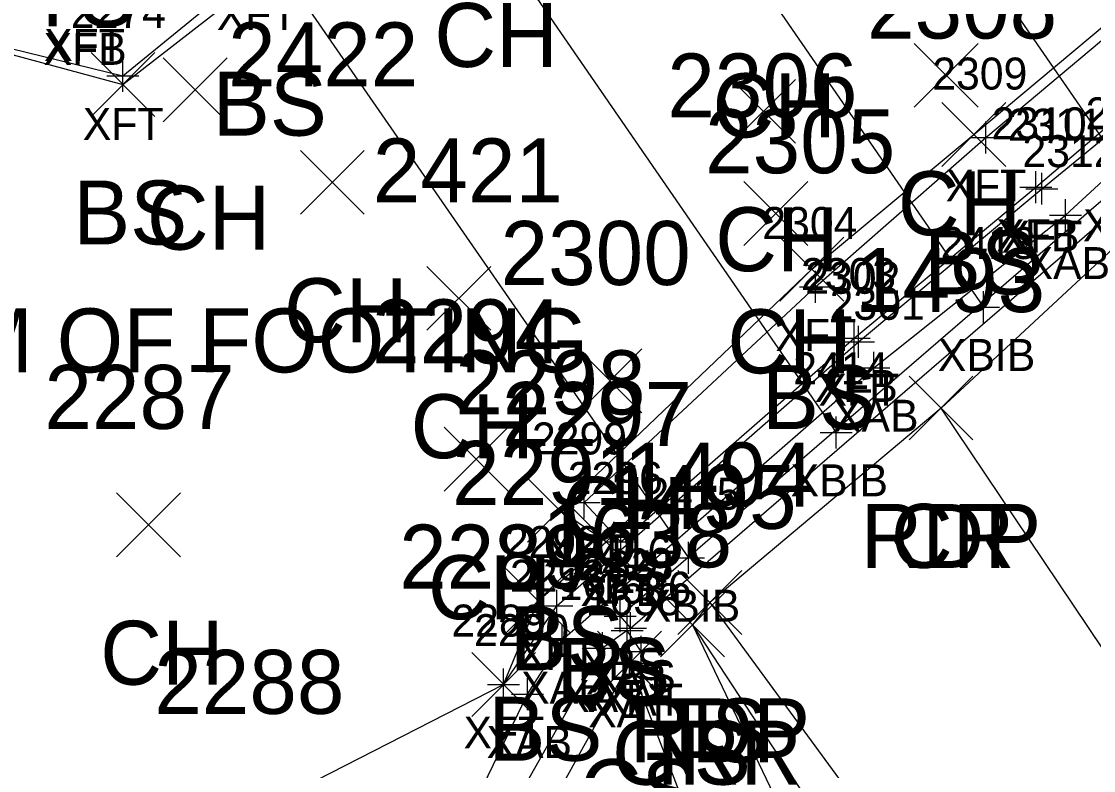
# Model space of a CAD drawing. Extents: x 1501299 to 1502485, y 381423 to 383765.
# Drawn here: x 1501597.62 to 1501631.17, y 383276.54 to 383299.97 of the extents above; entities that cross this region are included whole.
import ezdxf

# ---------------------------------------------------------------- set-up
doc = ezdxf.new("R2010")
doc.units = 0
for name, color, linetype in [('B_A', 7, 'Continuous'), ('B_I', 7, 'Continuous'), ('B_TIC', 7, 'Continuous'), ('BB', 7, 'Continuous'), ('BFT', 7, 'Continuous'), ('BSE', 7, 'Continuous'), ('BSUBM', 7, 'Continuous'), ('L_A', 7, 'Continuous'), ('L_C', 7, 'Continuous'), ('L_I', 7, 'Continuous'), ('L_TIC', 7, 'Continuous'), ('LELB', 7, 'Continuous'), ('P_A', 7, 'Continuous'), ('P_I', 7, 'Continuous'), ('P_TIC', 7, 'Continuous'), ('PET', 7, 'Continuous'), ('PRC', 7, 'Continuous'), ('R_A', 7, 'Continuous'), ('R_I', 7, 'Continuous'), ('R_TIC', 7, 'Continuous'), ('RGR', 7, 'Continuous')]:
    doc.layers.add(name, color=color, linetype=linetype)

msp = doc.modelspace()

# ---------------------------------------------------------------- linework, layer by layer
at = {"layer": 'B_TIC'}
for p, q in [((1501600.797, 383298.267), (1501600.873, 383298.267)), ((1501627.794, 383296.339), (1501627.87, 383296.339)), ((1501629.366, 383294.783), (1501629.442, 383294.783)), ((1501629.546, 383294.74), (1501629.622, 383294.74)), ((1501630.291, 383293.913), (1501630.367, 383293.913)), ((1501622.473, 383291.667), (1501622.548, 383291.667)), ((1501627.725, 383291.039), (1501627.801, 383291.039)), ((1501623.682, 383290.07), (1501623.758, 383290.07)), ((1501623.816, 383289.953), (1501623.892, 383289.953)), ((1501624.296, 383289.139), (1501624.372, 383289.139)), ((1501623.118, 383287.119), (1501623.193, 383287.119)), ((1501615.23, 383284.929), (1501615.305, 383284.929)), ((1501616.373, 383283.693), (1501616.448, 383283.693)), ((1501616.373, 383283.693), (1501616.448, 383283.693)), ((1501618.494, 383283.2), (1501618.57, 383283.2)), ((1501614.377, 383281.692), (1501614.453, 383281.692)), ((1501616.353, 383281.373), (1501616.428, 383281.373)), ((1501616.577, 383280.924), (1501616.653, 383280.924)), ((1501616.679, 383280.995), (1501616.755, 383280.995)), ((1501614.537, 383280.635), (1501614.613, 383280.635)), ((1501615.804, 383280.376), (1501615.88, 383280.376)), ((1501615.804, 383280.376), (1501615.88, 383280.376)), ((1501617.012, 383280.262), (1501617.088, 383280.262)), ((1501617.012, 383280.262), (1501617.088, 383280.262)), ((1501616.652, 383279.899), (1501616.727, 383279.899)), ((1501612.71, 383279.234), (1501612.786, 383279.234)), ((1501613.455, 383278.934), (1501613.53, 383278.934))]:
    msp.add_line(p, q, dxfattribs=at)
for points in [[(1501600.794, 383297.767), (1501600.794, 383298.767)], [(1501600.294, 383298.267), (1501601.294, 383298.267)], [(1501627.791, 383295.839), (1501627.791, 383296.839)], [(1501627.291, 383296.339), (1501628.291, 383296.339)], [(1501629.363, 383294.283), (1501629.363, 383295.283)], [(1501629.543, 383294.24), (1501629.543, 383295.24)], [(1501628.863, 383294.783), (1501629.863, 383294.783)], [(1501629.043, 383294.74), (1501630.043, 383294.74)], [(1501630.288, 383293.413), (1501630.288, 383294.413)], [(1501629.788, 383293.913), (1501630.788, 383293.913)], [(1501622.469, 383291.167), (1501622.469, 383292.167)], [(1501621.969, 383291.667), (1501622.969, 383291.667)], [(1501627.722, 383290.539), (1501627.722, 383291.539)], [(1501627.222, 383291.039), (1501628.222, 383291.039)], [(1501623.679, 383289.57), (1501623.679, 383290.57)], [(1501623.813, 383289.453), (1501623.813, 383290.453)], [(1501623.179, 383290.07), (1501624.179, 383290.07)], [(1501623.313, 383289.953), (1501624.313, 383289.953)], [(1501624.293, 383288.639), (1501624.293, 383289.639)], [(1501623.793, 383289.139), (1501624.793, 383289.139)], [(1501623.114, 383286.619), (1501623.114, 383287.619)], [(1501622.614, 383287.119), (1501623.614, 383287.119)], [(1501615.226, 383284.429), (1501615.226, 383285.429)], [(1501614.726, 383284.929), (1501615.726, 383284.929)], [(1501616.369, 383283.193), (1501616.369, 383284.193)], [(1501616.369, 383283.193), (1501616.369, 383284.193)], [(1501615.869, 383283.693), (1501616.869, 383283.693)], [(1501615.869, 383283.693), (1501616.869, 383283.693)], [(1501618.491, 383282.7), (1501618.491, 383283.7)], [(1501617.991, 383283.2), (1501618.991, 383283.2)], [(1501614.374, 383281.192), (1501614.374, 383282.192)], [(1501616.349, 383280.873), (1501616.349, 383281.873)], [(1501613.874, 383281.692), (1501614.874, 383281.692)], [(1501616.574, 383280.424), (1501616.574, 383281.424)], [(1501616.676, 383280.495), (1501616.676, 383281.495)], [(1501614.534, 383280.135), (1501614.534, 383281.135)], [(1501615.849, 383281.373), (1501616.849, 383281.373)], [(1501615.801, 383279.876), (1501615.801, 383280.876)], [(1501615.801, 383279.876), (1501615.801, 383280.876)], [(1501616.074, 383280.924), (1501617.074, 383280.924)], [(1501616.176, 383280.995), (1501617.176, 383280.995)], [(1501617.009, 383279.762), (1501617.009, 383280.762)], [(1501617.009, 383279.762), (1501617.009, 383280.762)], [(1501614.034, 383280.635), (1501615.034, 383280.635)], [(1501616.648, 383279.399), (1501616.648, 383280.399)], [(1501615.301, 383280.376), (1501616.301, 383280.376)], [(1501615.301, 383280.376), (1501616.301, 383280.376)], [(1501616.509, 383280.262), (1501617.509, 383280.262)], [(1501616.509, 383280.262), (1501617.509, 383280.262)], [(1501612.707, 383278.734), (1501612.707, 383279.734)], [(1501616.148, 383279.899), (1501617.148, 383279.899)], [(1501613.451, 383278.434), (1501613.451, 383279.434)], [(1501612.207, 383279.234), (1501613.207, 383279.234)], [(1501612.951, 383278.934), (1501613.951, 383278.934)]]:
    msp.add_lwpolyline(points, dxfattribs=at)
at = {"layer": 'BB'}
for points in [[(1501616.9, 383317.377), (1501632.264, 383295.097)], [(1501612.287, 383313.43), (1501627.722, 383291.039)], [(1501607.665, 383309.53), (1501623.114, 383287.119)], [(1501603.072, 383305.463), (1501618.491, 383283.2)]]:
    msp.add_lwpolyline(points, dxfattribs=at)
at = {"layer": 'BFT'}
for points in [[(1501590.258, 383300.858), (1501600.794, 383298.267), (1501604.985, 383301.7), (1501610.419, 383306.178), (1501616.429, 383311.032), (1501623.09, 383316.78), (1501624.747, 383320.366)], [(1501616.369, 383283.693), (1501615.226, 383284.929), (1501622.469, 383291.667), (1501627.791, 383296.339), (1501634.323, 383301.827), (1501643.966, 383300.613), (1501649.637, 383299.733), (1501649.406, 383298.057)], [(1501616.369, 383283.693), (1501623.679, 383290.07), (1501629.363, 383294.783), (1501635.405, 383299.935), (1501649.406, 383298.057)], [(1501612.707, 383279.234), (1501614.374, 383281.692), (1501623.813, 383289.953), (1501629.543, 383294.74), (1501635.454, 383299.572), (1501649.389, 383297.783), (1501649.431, 383296.917)]]:
    msp.add_lwpolyline(points, dxfattribs=at)
at = {"layer": 'BSE'}
msp.add_lwpolyline([(1501634.051, 383296.635), (1501616.349, 383281.373), (1501616.676, 383280.995), (1501634.378, 383296.256)], dxfattribs=at)
at = {"layer": 'BSUBM'}
for points in [[(1501610.098, 383268.035), (1501609.905, 383267.245), (1501608.382, 383268.462), (1501613.451, 383278.934), (1501614.534, 383280.635), (1501624.293, 383289.139), (1501630.288, 383293.913), (1501635.348, 383298.565), (1501649.431, 383296.917), (1501649.596, 383294.923)], [(1501617.009, 383280.262), (1501616.574, 383280.924), (1501615.801, 383280.376)], [(1501617.009, 383280.262), (1501616.648, 383279.899), (1501610.098, 383268.035), (1501609.218, 383268.708), (1501615.801, 383280.376)]]:
    msp.add_lwpolyline(points, dxfattribs=at)
at = {"layer": 'L_TIC'}
for points in [[(1501625.553, 383297.285), (1501627.553, 383299.285)], [(1501627.553, 383297.285), (1501625.553, 383299.285)], [(1501599.796, 383296.995), (1501601.796, 383298.995)], [(1501601.796, 383296.995), (1501599.796, 383298.995)], [(1501602.055, 383296.833), (1501604.055, 383298.833)], [(1501604.055, 383296.833), (1501602.055, 383298.833)], [(1501619.838, 383296.159), (1501621.838, 383298.159)], [(1501621.838, 383296.159), (1501619.838, 383298.159)], [(1501626.416, 383295.435), (1501628.416, 383297.435)], [(1501628.416, 383295.435), (1501626.416, 383297.435)], [(1501606.346, 383293.939), (1501608.346, 383295.939)], [(1501608.346, 383293.939), (1501606.346, 383295.939)], [(1501620.22, 383292.966), (1501622.22, 383294.966)], [(1501622.22, 383292.966), (1501620.22, 383294.966)], [(1501621.35, 383291.222), (1501623.35, 383293.222)], [(1501623.35, 383291.222), (1501621.35, 383293.222)], [(1501610.307, 383290.311), (1501612.307, 383292.311)], [(1501612.307, 383290.311), (1501610.307, 383292.311)], [(1501615.036, 383287.728), (1501617.036, 383289.728)], [(1501617.036, 383287.728), (1501615.036, 383289.728)], [(1501610.848, 383285.277), (1501612.848, 383287.277)], [(1501612.848, 383285.277), (1501610.848, 383287.277)], [(1501613.455, 383283.683), (1501615.455, 383285.683)], [(1501615.455, 383283.683), (1501613.455, 383285.683)], [(1501600.596, 383283.228), (1501602.596, 383285.228)], [(1501602.596, 383283.228), (1501600.596, 383285.228)], [(1501614.914, 383282.693), (1501616.914, 383284.693)], [(1501616.914, 383282.693), (1501614.914, 383284.693)], [(1501612.789, 383280.85), (1501614.789, 383282.85)], [(1501614.789, 383280.85), (1501612.789, 383282.85)], [(1501618.162, 383280.8), (1501620.162, 383282.8)], [(1501620.162, 383280.8), (1501618.162, 383282.8)], [(1501617.614, 383280.102), (1501619.614, 383282.102)], [(1501619.614, 383280.102), (1501617.614, 383282.102)], [(1501615.648, 383278.899), (1501617.648, 383280.899)], [(1501617.648, 383278.899), (1501615.648, 383280.899)], [(1501611.707, 383278.234), (1501613.707, 383280.234)], [(1501613.707, 383278.234), (1501611.707, 383280.234)]]:
    msp.add_lwpolyline(points, dxfattribs=at)
at = {"layer": 'LELB'}
for points in [[(1501590.761, 383266.457), (1501598.871, 383270.571), (1501605.035, 383275.317), (1501612.707, 383279.234), (1501613.789, 383281.85), (1501615.914, 383283.693), (1501614.455, 383284.683), (1501622.35, 383292.222), (1501627.416, 383296.435), (1501634.13, 383302.054), (1501643.772, 383300.983), (1501650.033, 383300.072), (1501651.493, 383297.792), (1501662.757, 383297.227), (1501671.557, 383298.422), (1501684.76, 383303.845), (1501698.893, 383313.194), (1501704.538, 383312.156), (1501711.847, 383316.203), (1501724.827, 383323.61), (1501744.215, 383336.813), (1501764.443, 383344.5)], [(1501498.194, 383229.3), (1501506.162, 383243.777), (1501514.118, 383255.518), (1501521.598, 383264.924), (1501530.006, 383266.909), (1501541.24, 383276.124), (1501565.518, 383288.263), (1501578.593, 383296.727), (1501585.352, 383299.258), (1501590.258, 383300.858), (1501600.796, 383297.995), (1501605.166, 383301.398), (1501610.699, 383306.054), (1501616.468, 383310.93), (1501623.409, 383316.642), (1501624.747, 383320.366)], [(1501619.162, 383281.8), (1501618.614, 383281.102), (1501625.909, 383269.987), (1501629.163, 383260.706), (1501626.947, 383253.594), (1501623.522, 383242.303), (1501612.249, 383228.196), (1501584.091, 383204.532), (1501565.556, 383192.677), (1501531.011, 383172.484)], [(1501616.648, 383279.899), (1501621.389, 383267.635), (1501624.053, 383260.203), (1501618.219, 383246.655), (1501610.438, 383240.687), (1501605.349, 383233.312)]]:
    msp.add_lwpolyline(points, dxfattribs=at)
at = {"layer": 'P_TIC'}
for points in [[(1501625.393, 383286.881), (1501627.393, 383288.881)], [(1501627.393, 383286.881), (1501625.393, 383288.881)], [(1501625.393, 383286.881), (1501627.393, 383288.881)], [(1501627.393, 383286.881), (1501625.393, 383288.881)], [(1501618.162, 383280.8), (1501620.162, 383282.8)], [(1501620.162, 383280.8), (1501618.162, 383282.8)]]:
    msp.add_lwpolyline(points, dxfattribs=at)
at = {"layer": 'PET'}
msp.add_lwpolyline([(1501787.994, 383066.094), (1501768.484, 383096.751), (1501754.41, 383116.891), (1501736.241, 383144.717), (1501720.749, 383167.971), (1501712.594, 383179.719), (1501694.383, 383207.646), (1501673.597, 383237.523), (1501647.754, 383273.845), (1501633.679, 383294.635), (1501626.393, 383287.881), (1501619.162, 383281.8), (1501626.926, 383271.201), (1501654.425, 383229.168), (1501675.697, 383198.288), (1501696.699, 383166.339)], dxfattribs=at)
at = {"layer": 'PRC'}
msp.add_lwpolyline([(1501960.612, 382718.648), (1501950.96, 382750.482), (1501934.965, 382791.852), (1501913.074, 382836.935), (1501889.309, 382881.383), (1501879.244, 382899.507), (1501856.391, 382940.32), (1501839.674, 382966.998), (1501816.055, 383004.313), (1501794.783, 383036.247), (1501769.812, 383075.158), (1501745.791, 383111.558), (1501729.435, 383136.001), (1501711.236, 383163.535), (1501694.816, 383188.199), (1501683.547, 383204.004), (1501664.644, 383231.239), (1501639.517, 383268.342), (1501626.393, 383287.881)], dxfattribs=at)
at = {"layer": 'R_TIC'}
for points in [[(1501617.614, 383280.102), (1501619.614, 383282.102)], [(1501619.614, 383280.102), (1501617.614, 383282.102)]]:
    msp.add_lwpolyline(points, dxfattribs=at)
at = {"layer": 'RGR'}
msp.add_lwpolyline([(1501618.614, 383281.102), (1501624.041, 383269.773)], dxfattribs=at)

# ---------------------------------------------------------------- texts
at = {"layer": 'B_A'}
for s, p in [('XFT', (1501603.729, 383299.7)), ('XFB', (1501598.311, 383298.612)), ('XFT', (1501598.328, 383298.737)), ('XFT', (1501599.538, 383296.267)), ('XFT', (1501626.535, 383294.339)), ('XBIB', (1501630.835, 383293.097)), ('XFB', (1501628.122, 383292.783)), ('XFT', (1501628.287, 383292.74)), ('XAB', (1501629.008, 383291.913)), ('XFT', (1501621.214, 383289.667)), ('XBIB', (1501626.293, 383289.039)), ('XFB', (1501622.439, 383288.07)), ('XFT', (1501622.557, 383287.953)), ('XAB', (1501623.013, 383287.139)), ('XBIB', (1501621.685, 383285.119)), ('XFT', (1501613.97, 383282.929)), ('XFT', (1501615.113, 383281.693)), ('XFB', (1501615.129, 383281.693)), ('XBIB', (1501617.062, 383281.2)), ('XFT', (1501613.118, 383279.692)), ('XBS', (1501615.089, 383279.373)), ('XAT', (1501615.279, 383278.924)), ('XBS', (1501615.416, 383278.995)), ('XAB', (1501613.254, 383278.635)), ('XAT', (1501614.505, 383278.376)), ('XAT', (1501614.505, 383278.376)), ('XAT', (1501615.714, 383278.262)), ('XAT', (1501615.714, 383278.262)), ('XAT', (1501615.353, 383277.899)), ('XFT', (1501611.451, 383277.234)), ('XAB', (1501612.172, 383276.934))]:
    msp.add_text(s, height=1, dxfattribs=at).set_placement(p)
at = {"layer": 'B_I'}
for s, p in [('2274', (1501599.164, 383299.767)), ('2309', (1501626.118, 383297.839)), ('2412', (1501630.918, 383296.597)), ('2310', (1501627.973, 383296.283)), ('2311', (1501628.48, 383296.24)), ('2312', (1501628.941, 383295.413)), ('2304', (1501620.8, 383293.167)), ('2413', (1501626.375, 383292.539)), ('2303', (1501622.01, 383291.57)), ('2302', (1501622.144, 383291.453)), ('2301', (1501622.907, 383290.639)), ('2414', (1501621.768, 383288.619)), ('2299', (1501613.592, 383286.429)), ('2296', (1501614.712, 383285.193)), ('2296', (1501614.712, 383285.193)), ('2415', (1501617.144, 383284.7)), ('2292', (1501612.744, 383283.192)), ('2416', (1501614.975, 383282.873)), ('2428', (1501615.046, 383282.495)), ('1637', (1501615.204, 383282.424)), ('2293', (1501612.904, 383282.135)), ('1687', (1501614.431, 383281.876)), ('1687', (1501614.431, 383281.876)), ('1636', (1501615.611, 383281.762)), ('1636', (1501615.611, 383281.762)), ('1638', (1501615.278, 383281.399)), ('2289', (1501611.073, 383280.734)), ('2290', (1501611.778, 383280.434))]:
    msp.add_text(s, height=1, dxfattribs=at).set_placement(p)
at = {"layer": 'L_A'}
for s, p in [('TS', (1501597.779, 383299.818)), ('CH', (1501610.539, 383298.546)), ('BS', (1501603.607, 383296.398)), ('CH', (1501619.242, 383296.345)), ('CH', (1501625.041, 383293.285)), ('BS', (1501599.237, 383292.995)), ('CH', (1501601.544, 383292.833)), ('CH', (1501619.326, 383292.159)), ('BS', (1501625.857, 383291.435)), ('CH', (1501605.835, 383289.939)), ('CH', (1501619.709, 383288.966)), ('BS', (1501620.791, 383287.222)), ('CH', (1501609.795, 383286.311)), ('CH', (1501614.524, 383283.728)), ('CH', (1501610.336, 383281.277)), ('BS', (1501612.896, 383279.683)), ('CH', (1501600.084, 383279.228)), ('BS', (1501614.355, 383278.693)), ('BS', (1501612.23, 383276.85)), ('TS', (1501617.571, 383276.8)), ('TS', (1501617.024, 383276.102)), ('CS', (1501615.089, 383274.899))]:
    msp.add_text(s, height=2, dxfattribs=at).set_placement(p)
at = {"layer": 'L_C'}
msp.add_text('AT BOTTOM OF FOOTING', height=2, dxfattribs=at).set_placement((1501582.379, 383288.995))
at = {"layer": 'L_I'}
for s, p in [('2308', (1501624.078, 383299.435)), ('2422', (1501604.087, 383297.939)), ('2306', (1501617.827, 383296.966)), ('2305', (1501619.011, 383295.222)), ('2421', (1501608.614, 383294.311)), ('2300', (1501612.611, 383291.728)), ('2294', (1501608.588, 383289.277)), ('2298', (1501611.196, 383287.683)), ('2287', (1501598.336, 383287.228)), ('2297', (1501612.654, 383286.693)), ('2291', (1501611.096, 383284.85)), ('1494', (1501616.469, 383284.8)), ('1495', (1501615.921, 383284.102)), ('1638', (1501613.908, 383282.899)), ('2289', (1501609.439, 383282.234)), ('2288', (1501601.775, 383278.317))]:
    msp.add_text(s, height=2, dxfattribs=at).set_placement(p)
at = {"layer": 'P_A'}
for s, p in [('RDP', (1501623.881, 383282.881)), ('CR', (1501624.826, 383282.881)), ('RDP', (1501616.65, 383276.8))]:
    msp.add_text(s, height=2, dxfattribs=at).set_placement(p)
at = {"layer": 'P_I'}
for s, p in [('1493', (1501623.7, 383290.881)), ('1493', (1501623.7, 383290.881)), ('1494', (1501616.469, 383284.8))]:
    msp.add_text(s, height=2, dxfattribs=at).set_placement(p)
at = {"layer": 'R_A'}
msp.add_text('GRR', height=2, dxfattribs=at).set_placement((1501616.102, 383276.102))
at = {"layer": 'R_I'}
msp.add_text('1495', height=2, dxfattribs=at).set_placement((1501615.921, 383284.102))

doc.saveas('drawing.dxf')
